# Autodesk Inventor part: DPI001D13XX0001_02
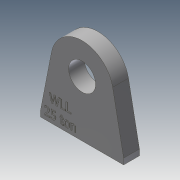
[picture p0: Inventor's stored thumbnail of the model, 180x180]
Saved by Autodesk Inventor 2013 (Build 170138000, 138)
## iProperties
Created: 2014-02
Part Number: DPI001D13XX0001_02
Material: ASTM-A 36
Description: CHAPA - 225 x 200 x 1.1/2"
Document SubType Name: Modeling
Designer: luiz.parente
Density: 7.85 g/cm^3
Mass: 9367.9 g
Surface Area: 979.497 cm^2
Volume: 1193.36 cm^3
Author: luiz.parente
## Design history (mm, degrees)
sketch "Sketch1"
  geometry: L1 (-73.594, 14.453)-(-100, -120); L2 (-100, -120)-(-100, -150); L3 (-100, -150)-(100, -150); L4 (100, -120)-(73.594, 14.453); L5 (100, -120)-(100, -150); C1 r 32.5 at (0, 0); A1 r 75 centre (0, 0) between (73.594, 14.453) and (-73.594, 14.453); 2 further points
  constraints: 10 end point, 2 centre point, 2 coincident, 2 perpendicular, 2 point on circle, 2 tangent, 1 midpoint, 1 vertical, 1 vertical alignment
  dimensions: "d0" = 150 diameter of A1; "d1" = 65 diameter of C1; "d3" = 30 distance of L1.end L2.end; "d4" = 30 distance of L4.start L3.end (= d3); "d5" = 150 distance from line of A1.centre L3; "d6" = 200 distance of L2.end L3.end
extrude "Extrusion1" new body sketch "Sketch1" stored distance "d7" = 38.1; taper "d8" = 0 deg
sketch "Sketch2"
  geometry: L1 (0, 38.1)-(0, 0) reference; L2 (-30, 38.1)-(0, 38.1) reference; L3 (0, 0)-(-30, 0) reference; L4 (0, 15.8)-(-15.8, 0); L5 (0, 22.3)-(-15.8, 38.1); L6 (0, 22.3)-(0, 15.8); 2 further points
  constraints: 6 end point, 4 point on line, 2 midpoint, 1 perpendicular
  dimensions: "d9" = 6.5 distance of L4.start L5.start; "d10" = 45 deg angle of L1 L4; "d11" = 45 deg angle of L1 L5 (= d10)
extrude "Extrusion2" cut sketch "Sketch2" stored distance "d12" = 10; taper "d13" = 0 deg
sketch "Sketch3"
  geometry: L1 (-92, -71.2)-(-12.655, -71.2); L2 (-12.655, -71.2)-(-12.655, -124.2); L3 (-12.655, -124.2)-(-92, -124.2); L4 (-92, -124.2)-(-92, -71.2); 1 further point
  constraints: 2 other
  dimensions: "d22" = 10 distance from line of point (-100, -134.2) L3; "d28" = 8 horizontal distance of point (-100, -134.2) L3.end; "d37" = 53 distance of L3.end L1.start
emboss "Emboss1" sketch "Sketch3" dims "d0" = 150, "d1" = 65, "d3" = 30, "d4" = 30 (= d3), "d5" = 150, "d6" = 200, "d14" = 1, "d15" = 0
chamfer "Chamfer1" distance "d16" = 15.8; stored, may be unused: second distance "d17" = 2, angle "d18" = 45 deg
sketch "Sketch4"
  geometry: L1 (90, 71.2)-(9.106, 71.2); L2 (9.106, 71.2)-(9.106, 124.2); L3 (9.106, 124.2)-(90, 124.2); L4 (90, 124.2)-(90, 71.2); 1 further point
  constraints: 2 other
  dimensions: "d32" = 10 horizontal distance of point (100, 134.2) L3.end; "d33" = 10 horizontal distance of point (100, 134.2) L3.end; "d36" = 53 distance of L3.end L1.start
emboss "Emboss2" sketch "Sketch4" dims "d0" = 150, "d1" = 65, "d3" = 30, "d4" = 30 (= d3), "d5" = 150, "d6" = 200, "d30" = 1, "d31" = 0
body "Solid1"
